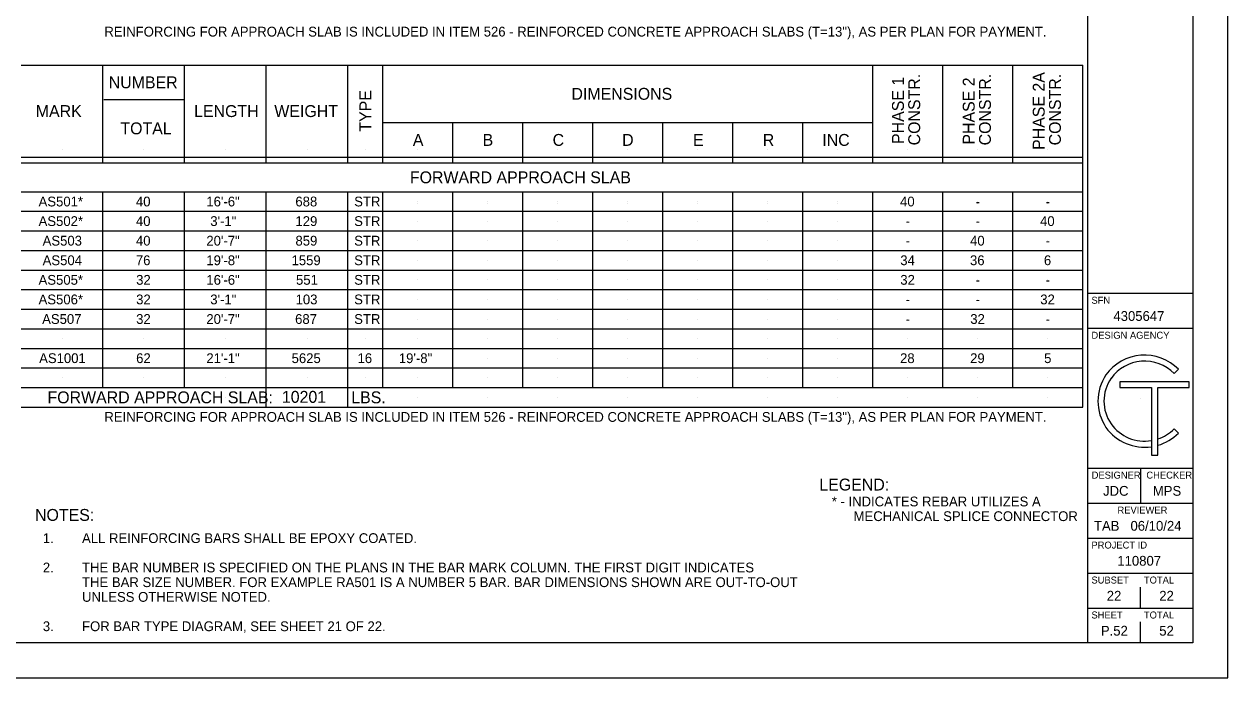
# Model space of a CAD drawing. Extents: x 0 to 34, y 0 to 22.
# Drawn here: x 16.8 to 34, y 0 to 9.35 of the extents above; entities that cross this region are included whole.
import ezdxf

# ---------------------------------------------------------------- set-up
doc = ezdxf.new("R2010")
doc.units = 0
for name, color, linetype in [('BR_P_Gen_Text', 7, 'Continuous'), ('SH_Border', 7, 'Continuous'), ('SH_Cut_Line', 7, 'Continuous'), ('SH_Data', 7, 'Continuous'), ('SH_Text', 7, 'Continuous')]:
    doc.layers.add(name, color=color, linetype=linetype)

msp = doc.modelspace()

# ---------------------------------------------------------------- linework, layer by layer
at = {"layer": 'BR_P_Gen_Text'}
for p, q in [((16.76, 8.763), (31.927, 8.764)), ((17.927, 7.363), (17.927, 8.763)), ((19.094, 7.363), (19.094, 8.763)), ((20.26, 7.364), (20.26, 8.763)), ((21.427, 7.364), (21.427, 8.763)), ((21.927, 7.364), (21.927, 8.763)), ((28.927, 7.363), (28.927, 8.764)), ((29.927, 7.363), (29.927, 8.764)), ((30.927, 7.363), (30.927, 8.764)), ((31.927, 3.872), (31.927, 8.764)), ((17.941, 8.269), (19.094, 8.269)), ((21.927, 7.94), (28.927, 7.94)), ((22.927, 7.363), (22.927, 7.94)), ((23.927, 7.363), (23.927, 7.94)), ((24.927, 7.363), (24.927, 7.94)), ((25.927, 7.363), (25.927, 7.94)), ((26.927, 7.363), (26.927, 7.94)), ((27.927, 7.363), (27.927, 7.94)), ((16.76, 7.446), (31.927, 7.446)), ((17.344, 7.561), (17.344, 7.561)), ((17.344, 7.561), (17.344, 7.561)), ((18.51, 7.561), (18.51, 7.561)), ((18.51, 7.561), (18.51, 7.561)), ((19.677, 7.561), (19.677, 7.561)), ((19.677, 7.561), (19.677, 7.561)), ((20.844, 7.561), (20.844, 7.561)), ((20.844, 7.561), (20.844, 7.561)), ((21.677, 7.561), (21.677, 7.561)), ((21.677, 7.561), (21.677, 7.561)), ((22.427, 7.561), (22.427, 7.561)), ((22.427, 7.561), (22.427, 7.561)), ((24.427, 7.561), (24.427, 7.561)), ((24.427, 7.561), (24.427, 7.561)), ((25.427, 7.561), (25.427, 7.561)), ((25.427, 7.561), (25.427, 7.561)), ((26.427, 7.561), (26.427, 7.561)), ((26.427, 7.561), (26.427, 7.561)), ((27.427, 7.561), (27.427, 7.561)), ((27.427, 7.561), (27.427, 7.561)), ((28.427, 7.561), (28.427, 7.561)), ((28.427, 7.561), (28.427, 7.561)), ((29.427, 7.561), (29.427, 7.561)), ((30.427, 7.561), (30.427, 7.561)), ((31.427, 7.561), (31.427, 7.561)), ((16.76, 7.363), (31.927, 7.363)), ((22.844, 7.158), (22.844, 7.158)), ((16.76, 6.952), (31.927, 6.952)), ((17.927, 4.152), (17.927, 6.952)), ((19.094, 4.152), (19.094, 6.952)), ((20.26, 3.872), (20.26, 6.952)), ((21.427, 3.872), (21.427, 6.952)), ((21.927, 4.152), (21.927, 6.952)), ((22.927, 4.152), (22.927, 6.952)), ((23.927, 4.152), (23.927, 6.952)), ((24.927, 4.152), (24.927, 6.952)), ((25.927, 4.152), (25.927, 6.952)), ((26.927, 4.152), (26.927, 6.952)), ((27.927, 4.152), (27.927, 6.952)), ((28.927, 4.152), (28.927, 6.952)), ((29.927, 4.152), (29.927, 6.952)), ((30.927, 4.152), (30.927, 6.952)), ((17.344, 6.812), (17.344, 6.812)), ((17.344, 6.778), (17.344, 6.778)), ((17.344, 6.778), (17.344, 6.778)), ((18.51, 6.812), (18.51, 6.812)), ((18.51, 6.778), (18.51, 6.778)), ((18.51, 6.778), (18.51, 6.778)), ((19.677, 6.812), (19.677, 6.812)), ((19.677, 6.778), (19.677, 6.778)), ((19.677, 6.778), (19.677, 6.778)), ((20.844, 6.812), (20.844, 6.812)), ((20.844, 6.778), (20.844, 6.778)), ((20.844, 6.778), (20.844, 6.778)), ((21.677, 6.812), (21.677, 6.812)), ((21.677, 6.778), (21.677, 6.778)), ((21.677, 6.778), (21.677, 6.778)), ((22.427, 6.812), (22.427, 6.812)), ((22.427, 6.778), (22.427, 6.778)), ((23.427, 6.812), (23.427, 6.812)), ((23.427, 6.778), (23.427, 6.778)), ((24.427, 6.812), (24.427, 6.812)), ((24.427, 6.778), (24.427, 6.778)), ((25.427, 6.812), (25.427, 6.812)), ((25.427, 6.778), (25.427, 6.778)), ((26.427, 6.812), (26.427, 6.812)), ((26.427, 6.778), (26.427, 6.778)), ((27.427, 6.812), (27.427, 6.812)), ((27.427, 6.778), (27.427, 6.778)), ((28.427, 6.812), (28.427, 6.812)), ((28.427, 6.778), (28.427, 6.778)), ((29.427, 6.812), (29.427, 6.812)), ((29.427, 6.778), (29.427, 6.778)), ((30.427, 6.812), (30.427, 6.812)), ((30.427, 6.778), (30.427, 6.778)), ((31.427, 6.812), (31.427, 6.812)), ((31.427, 6.778), (31.427, 6.778)), ((16.76, 6.672), (31.927, 6.672)), ((16.76, 6.392), (31.927, 6.392)), ((17.344, 6.532), (17.344, 6.532)), ((18.51, 6.532), (18.51, 6.532)), ((19.677, 6.532), (19.677, 6.532)), ((20.844, 6.532), (20.844, 6.532)), ((21.677, 6.532), (21.677, 6.532)), ((22.427, 6.532), (22.427, 6.532)), ((23.427, 6.532), (23.427, 6.532)), ((24.427, 6.532), (24.427, 6.532)), ((25.427, 6.532), (25.427, 6.532)), ((26.427, 6.532), (26.427, 6.532)), ((27.427, 6.532), (27.427, 6.532)), ((28.427, 6.532), (28.427, 6.532)), ((29.427, 6.532), (29.427, 6.532)), ((30.427, 6.532), (30.427, 6.532)), ((31.427, 6.532), (31.427, 6.532)), ((17.344, 6.252), (17.344, 6.252)), ((18.51, 6.252), (18.51, 6.252)), ((19.677, 6.252), (19.677, 6.252)), ((20.844, 6.252), (20.844, 6.252)), ((21.677, 6.252), (21.677, 6.252)), ((22.427, 6.252), (22.427, 6.252)), ((23.427, 6.252), (23.427, 6.252)), ((24.427, 6.252), (24.427, 6.252)), ((25.427, 6.252), (25.427, 6.252)), ((26.427, 6.252), (26.427, 6.252)), ((27.427, 6.252), (27.427, 6.252)), ((28.427, 6.252), (28.427, 6.252)), ((30.427, 6.252), (30.427, 6.252)), ((31.427, 6.252), (31.427, 6.252)), ((16.76, 6.112), (31.927, 6.112)), ((17.344, 5.972), (17.344, 5.972)), ((22.427, 5.972), (22.427, 5.972)), ((23.427, 5.972), (23.427, 5.972)), ((24.427, 5.972), (24.427, 5.972)), ((25.427, 5.972), (25.427, 5.972)), ((26.427, 5.972), (26.427, 5.972)), ((27.427, 5.972), (27.427, 5.972)), ((28.427, 5.972), (28.427, 5.972)), ((29.427, 5.972), (29.427, 5.972)), ((30.427, 5.972), (30.427, 5.972)), ((31.427, 5.972), (31.427, 5.972)), ((16.76, 5.832), (31.927, 5.832)), ((17.344, 5.692), (17.344, 5.692)), ((18.51, 5.692), (18.51, 5.692)), ((19.677, 5.692), (19.677, 5.692)), ((20.844, 5.692), (20.844, 5.692)), ((21.677, 5.692), (21.677, 5.692)), ((22.427, 5.692), (22.427, 5.692)), ((23.427, 5.692), (23.427, 5.692)), ((24.427, 5.692), (24.427, 5.692)), ((25.427, 5.692), (25.427, 5.692)), ((26.427, 5.692), (26.427, 5.692)), ((27.427, 5.692), (27.427, 5.692)), ((28.427, 5.692), (28.427, 5.692)), ((29.427, 5.692), (29.427, 5.692)), ((30.427, 5.692), (30.427, 5.692)), ((31.427, 5.692), (31.427, 5.692)), ((16.76, 5.552), (31.927, 5.552)), ((17.344, 5.412), (17.344, 5.412)), ((18.51, 5.412), (18.51, 5.412)), ((19.677, 5.412), (19.677, 5.412)), ((20.844, 5.412), (20.844, 5.412)), ((21.677, 5.412), (21.677, 5.412)), ((22.427, 5.412), (22.427, 5.412)), ((23.427, 5.412), (23.427, 5.412)), ((24.427, 5.412), (24.427, 5.412)), ((25.427, 5.412), (25.427, 5.412)), ((26.427, 5.412), (26.427, 5.412)), ((27.427, 5.412), (27.427, 5.412)), ((28.427, 5.412), (28.427, 5.412)), ((29.427, 5.412), (29.427, 5.412)), ((30.427, 5.412), (30.427, 5.412)), ((31.427, 5.412), (31.427, 5.412)), ((16.76, 5.272), (31.927, 5.272)), ((16.76, 4.992), (31.927, 4.992)), ((17.344, 5.132), (17.344, 5.132)), ((18.51, 5.132), (18.51, 5.132)), ((19.677, 5.132), (19.677, 5.132)), ((20.844, 5.132), (20.844, 5.132)), ((21.677, 5.132), (21.677, 5.132)), ((22.427, 5.132), (22.427, 5.132)), ((23.427, 5.132), (23.427, 5.132)), ((24.427, 5.132), (24.427, 5.132)), ((25.427, 5.132), (25.427, 5.132)), ((26.427, 5.132), (26.427, 5.132)), ((27.427, 5.132), (27.427, 5.132)), ((28.427, 5.132), (28.427, 5.132)), ((29.427, 5.132), (29.427, 5.132)), ((30.427, 5.132), (30.427, 5.132)), ((31.427, 5.132), (31.427, 5.132)), ((17.344, 4.852), (17.344, 4.852)), ((17.344, 4.852), (17.344, 4.852)), ((18.51, 4.852), (18.51, 4.852)), ((18.51, 4.852), (18.51, 4.852)), ((19.677, 4.852), (19.677, 4.852)), ((19.677, 4.852), (19.677, 4.852)), ((20.844, 4.852), (20.844, 4.852)), ((20.844, 4.852), (20.844, 4.852)), ((21.677, 4.852), (21.677, 4.852)), ((21.677, 4.852), (21.677, 4.852)), ((22.427, 4.852), (22.427, 4.852)), ((22.427, 4.852), (22.427, 4.852)), ((23.427, 4.852), (23.427, 4.852)), ((23.427, 4.852), (23.427, 4.852)), ((24.427, 4.852), (24.427, 4.852)), ((24.427, 4.852), (24.427, 4.852)), ((25.427, 4.852), (25.427, 4.852)), ((25.427, 4.852), (25.427, 4.852)), ((26.427, 4.852), (26.427, 4.852)), ((26.427, 4.852), (26.427, 4.852)), ((27.427, 4.852), (27.427, 4.852)), ((27.427, 4.852), (27.427, 4.852)), ((28.427, 4.852), (28.427, 4.852)), ((28.427, 4.852), (28.427, 4.852)), ((29.427, 4.852), (29.427, 4.852)), ((30.427, 4.852), (30.427, 4.852)), ((31.427, 4.852), (31.427, 4.852)), ((16.76, 4.712), (31.927, 4.712)), ((17.344, 4.572), (17.344, 4.572)), ((17.344, 4.572), (17.344, 4.572)), ((18.51, 4.572), (18.51, 4.572)), ((18.51, 4.572), (18.51, 4.572)), ((19.677, 4.572), (19.677, 4.572)), ((19.677, 4.572), (19.677, 4.572)), ((20.844, 4.572), (20.844, 4.572)), ((20.844, 4.572), (20.844, 4.572)), ((21.677, 4.572), (21.677, 4.572)), ((21.677, 4.572), (21.677, 4.572)), ((22.427, 4.572), (22.427, 4.572)), ((22.427, 4.572), (22.427, 4.572)), ((23.427, 4.572), (23.427, 4.572)), ((23.427, 4.572), (23.427, 4.572)), ((24.427, 4.572), (24.427, 4.572)), ((24.427, 4.572), (24.427, 4.572)), ((25.427, 4.572), (25.427, 4.572)), ((25.427, 4.572), (25.427, 4.572)), ((26.427, 4.572), (26.427, 4.572)), ((26.427, 4.572), (26.427, 4.572)), ((27.427, 4.572), (27.427, 4.572)), ((27.427, 4.572), (27.427, 4.572)), ((28.427, 4.572), (28.427, 4.572)), ((28.427, 4.572), (28.427, 4.572)), ((29.427, 4.572), (29.427, 4.572)), ((29.427, 4.572), (29.427, 4.572)), ((30.427, 4.572), (30.427, 4.572)), ((30.427, 4.572), (30.427, 4.572)), ((31.427, 4.572), (31.427, 4.572)), ((31.427, 4.572), (31.427, 4.572)), ((16.76, 4.432), (31.927, 4.432)), ((16.76, 4.152), (31.927, 4.152)), ((17.344, 4.292), (17.344, 4.292)), ((18.51, 4.292), (18.51, 4.292)), ((19.677, 4.292), (19.677, 4.292)), ((20.844, 4.292), (20.844, 4.292)), ((21.677, 4.292), (21.677, 4.292)), ((22.427, 4.292), (22.427, 4.292)), ((23.427, 4.292), (23.427, 4.292)), ((24.427, 4.292), (24.427, 4.292)), ((25.427, 4.292), (25.427, 4.292)), ((26.427, 4.292), (26.427, 4.292)), ((27.427, 4.292), (27.427, 4.292)), ((28.427, 4.292), (28.427, 4.292)), ((29.427, 4.292), (29.427, 4.292)), ((30.427, 4.292), (30.427, 4.292)), ((31.427, 4.292), (31.427, 4.292)), ((17.344, 4.012), (17.344, 4.012)), ((18.51, 4.012), (18.51, 4.012)), ((19.677, 4.012), (19.677, 4.012)), ((20.844, 4.012), (20.844, 4.012)), ((21.677, 4.012), (21.677, 4.012)), ((22.427, 4.012), (22.427, 4.012)), ((23.427, 4.012), (23.427, 4.012)), ((24.427, 4.012), (24.427, 4.012)), ((25.427, 4.012), (25.427, 4.012)), ((26.427, 4.012), (26.427, 4.012)), ((27.427, 4.012), (27.427, 4.012)), ((28.427, 4.012), (28.427, 4.012)), ((29.427, 4.012), (29.427, 4.012)), ((30.427, 4.012), (30.427, 4.012)), ((31.427, 4.012), (31.427, 4.012)), ((16.76, 3.872), (31.927, 3.872))]:
    msp.add_line(p, q, dxfattribs=at)
at = {"layer": 'SH_Border'}
for p, q in [((32, 0.5), (32, 21.5)), ((32, 5.5), (33.5, 5.5)), ((32, 5), (33.5, 5)), ((32, 3), (33.5, 3)), ((32.75, 3), (32.75, 2.5)), ((32, 2.5), (33.5, 2.5)), ((32, 2), (33.5, 2)), ((32, 1.5), (33.5, 1.5)), ((32, 1), (33.5, 1))]:
    msp.add_line(p, q, dxfattribs=at)
msp.add_lwpolyline([(1.5, 21.5), (33.5, 21.5), (33.5, 0.5), (1.5, 0.5)], close=True, dxfattribs=at)
at = {"layer": 'SH_Cut_Line'}
msp.add_lwpolyline([(0, 0), (34, 0), (34, 22), (0, 22)], close=True, dxfattribs=at)
at = {"layer": 'SH_Data'}
for p, q in [((32.75, 4), (32.75, 4)), ((32.75, 1), (32.75, 1.3)), ((32.75, 0.5), (32.75, 0.8)), ((32.375, 0.675), (32.375, 0.675))]:
    msp.add_line(p, q, dxfattribs=at)
at = {"layer": 'SH_Text'}
for p, q in [((33.293, 4.415), (33.231, 4.354)), ((33.293, 4.415), (33.231, 4.354)), ((33.446, 4.234), (32.458, 4.234)), ((32.458, 4.234), (32.458, 4.152)), ((32.458, 4.152), (32.907, 4.152)), ((32.907, 4.152), (32.907, 3.186)), ((33, 3.186), (33, 4.152)), ((33, 4.152), (33.446, 4.152)), ((33.446, 4.152), (33.446, 4.234)), ((33.231, 3.562), (33.293, 3.5)), ((33.231, 3.562), (33.293, 3.5)), ((32.907, 3.394), (32.907, 3.306)), ((32.907, 3.394), (32.907, 3.306)), ((33, 3.326), (33, 3.417)), ((33, 3.326), (33, 3.417)), ((32.907, 3.186), (33, 3.186))]:
    msp.add_line(p, q, dxfattribs=at)
msp.add_lwpolyline([(32.907, 4.152), (32.907, 3.186), (33, 3.186), (33, 4.152), (33.446, 4.152), (33.446, 4.234), (32.458, 4.234), (32.458, 4.152)], close=True, dxfattribs=at)
for centre, radius, start, end in [((32.81, 3.936), 0.68, 44.7027, 144.3276), ((32.81, 3.936), 0.68, 44.7027, 144.3276), ((32.81, 3.936), 0.593, 44.7362, 144.1102), ((32.81, 3.936), 0.593, 44.7362, 144.1102), ((32.808, 3.958), 0.666, 145.7329, 214.2671), ((32.808, 3.958), 0.666, 145.7329, 214.2671), ((32.808, 3.958), 0.579, 145.7266, 214.2734), ((32.808, 3.958), 0.579, 145.7266, 214.2734), ((32.81, 3.979), 0.593, 215.8898, 279.4882), ((32.81, 3.979), 0.593, 215.8898, 279.4882), ((32.81, 3.979), 0.68, 215.6724, 278.2613), ((32.81, 3.979), 0.68, 215.6724, 278.2613), ((32.81, 3.979), 0.593, 288.6992, 315.2638), ((32.81, 3.979), 0.593, 288.6992, 315.2638), ((32.81, 3.979), 0.68, 286.2291, 315.2973), ((32.81, 3.979), 0.68, 286.2291, 315.2973)]:
    msp.add_arc(centre, radius, start, end, dxfattribs=at)

# ---------------------------------------------------------------- texts
at = {"layer": 'BR_P_Gen_Text'}
for s, height, p in [('REINFORCING FOR APPROACH SLAB IS INCLUDED IN ITEM 526 - REINFORCED CONCRETE APPROACH SLABS (T=13"), AS PER PLAN FOR PAYMENT.', 0.14, (17.948, 9.171)), ('NUMBER', 0.17, (18.01, 8.431)), ('DIMENSIONS', 0.17, (24.621, 8.267)), ('MARK', 0.17, (16.968, 8.02)), ('LENGTH', 0.17, (19.23, 8.02)), ('WEIGHT', 0.17, (20.376, 8.02)), ('TOTAL', 0.17, (18.177, 7.773)), ('A', 0.17, (22.355, 7.608)), ('B', 0.17, (23.352, 7.608)), ('C', 0.17, (24.352, 7.608)), ('D', 0.17, (25.345, 7.608)), ('E', 0.17, (26.358, 7.608)), ('R', 0.17, (27.354, 7.608)), ('INC', 0.17, (28.204, 7.608)), ('FORWARD APPROACH SLAB', 0.17, (22.313, 7.073)), ('AS501*', 0.14, (17.008, 6.742)), ('40', 0.14, (18.399, 6.742)), ('16\'-6"', 0.14, (19.405, 6.742)), ('688', 0.14, (20.677, 6.742)), ('STR', 0.14, (21.517, 6.742)), ('40', 0.14, (29.316, 6.742)), ('-', 0.14, (30.396, 6.742)), ('-', 0.14, (31.396, 6.742)), ('AS502*', 0.14, (17.008, 6.462)), ('40', 0.14, (18.399, 6.462)), ('3\'-1"', 0.14, (19.461, 6.462)), ('129', 0.14, (20.678, 6.462)), ('STR', 0.14, (21.517, 6.462)), ('40', 0.14, (31.316, 6.462)), ('-', 0.14, (29.396, 6.462)), ('-', 0.14, (30.396, 6.462)), ('AS503', 0.14, (17.066, 6.182)), ('40', 0.14, (18.399, 6.182)), ('20\'-7"', 0.14, (19.405, 6.182)), ('859', 0.14, (20.678, 6.182)), ('STR', 0.14, (21.517, 6.182)), ('-', 0.14, (29.396, 6.182)), ('40', 0.14, (30.316, 6.182)), ('-', 0.14, (31.396, 6.182)), ('AS504', 0.14, (17.066, 5.902)), ('76', 0.14, (18.398, 5.902)), ('19\'-8"', 0.14, (19.405, 5.902)), ('1559', 0.14, (20.622, 5.902)), ('STR', 0.14, (21.517, 5.902)), ('34', 0.14, (29.319, 5.902)), ('36', 0.14, (30.315, 5.902)), ('6', 0.14, (31.371, 5.902)), ('AS505*', 0.14, (17.008, 5.622)), ('32', 0.14, (18.402, 5.622)), ('16\'-6"', 0.14, (19.405, 5.622)), ('551', 0.14, (20.686, 5.622)), ('STR', 0.14, (21.517, 5.622)), ('32', 0.14, (29.319, 5.622)), ('-', 0.14, (30.396, 5.622)), ('-', 0.14, (31.396, 5.622)), ('AS506*', 0.14, (17.008, 5.342)), ('32', 0.14, (18.402, 5.342)), ('3\'-1"', 0.14, (19.461, 5.342)), ('103', 0.14, (20.68, 5.342)), ('STR', 0.14, (21.517, 5.342)), ('-', 0.14, (29.396, 5.342)), ('-', 0.14, (30.396, 5.342)), ('32', 0.14, (31.319, 5.342)), ('AS507', 0.14, (17.059, 5.062)), ('32', 0.14, (18.402, 5.062)), ('20\'-7"', 0.14, (19.405, 5.062)), ('687', 0.14, (20.673, 5.062)), ('STR', 0.14, (21.517, 5.062)), ('32', 0.14, (30.319, 5.062)), ('-', 0.14, (29.396, 5.062)), ('-', 0.14, (31.396, 5.062)), ('AS1001', 0.14, (17.016, 4.502)), ('62', 0.14, (18.402, 4.502)), ('21\'-1"', 0.14, (19.405, 4.502)), ('5625', 0.14, (20.623, 4.502)), ('16', 0.14, (21.565, 4.502)), ('19\'-8"', 0.14, (22.155, 4.502)), ('28', 0.14, (29.316, 4.502)), ('29', 0.14, (30.317, 4.502)), ('5', 0.14, (31.374, 4.502)), ('FORWARD APPROACH SLAB:', 0.17, (17.135, 3.927)), ('10201', 0.17, (20.484, 3.934)), ('LBS.', 0.17, (21.475, 3.927)), ('REINFORCING FOR APPROACH SLAB IS INCLUDED IN ITEM 526 - REINFORCED CONCRETE APPROACH SLABS (T=13"), AS PER PLAN FOR PAYMENT.', 0.14, (17.948, 3.662)), ('LEGEND:', 0.17, (28.163, 2.68)), ('* - INDICATES REBAR UTILIZES A', 0.14, (28.34, 2.453)), ('NOTES:', 0.17, (16.957, 2.246)), ('      MECHANICAL SPLICE CONNECTOR', 0.14, (28.34, 2.243)), ('1.', 0.14, (17.069, 1.929)), ('ALL REINFORCING BARS SHALL BE EPOXY COATED.', 0.14, (17.629, 1.929)), ('2.', 0.14, (17.069, 1.509)), ('THE BAR NUMBER IS SPECIFIED ON THE PLANS IN THE BAR MARK COLUMN. THE FIRST DIGIT INDICATES', 0.14, (17.629, 1.509)), ('THE BAR SIZE NUMBER. FOR EXAMPLE RA501 IS A NUMBER 5 BAR. BAR DIMENSIONS SHOWN ARE OUT-TO-OUT', 0.14, (17.629, 1.299)), ('UNLESS OTHERWISE NOTED.', 0.14, (17.629, 1.089)), ('3.', 0.14, (17.069, 0.669)), ('FOR BAR TYPE DIAGRAM, SEE SHEET 21 OF 22.', 0.14, (17.629, 0.669))]:
    msp.add_text(s, height=height, dxfattribs=at).set_placement(p)
for s, p in [('CONSTR.', (29.603, 7.615)), ('CONSTR.', (30.614, 7.615)), ('PHASE 2A', (31.382, 7.55)), ('CONSTR.', (31.614, 7.615)), ('PHASE 1', (29.371, 7.635)), ('PHASE 2', (30.382, 7.626)), ('TYPE', (21.762, 7.811))]:
    msp.add_text(s, height=0.17, rotation=90, dxfattribs=at).set_placement(p)
at = {"layer": 'SH_Data'}
for s, height, p in [('SFN', 0.1, (32.05, 5.35)), ('4305647', 0.14, (32.364, 5.105)), ('DESIGN AGENCY', 0.1, (32.05, 4.85)), ('DESIGNER', 0.1, (32.054, 2.85)), ('CHECKER', 0.1, (32.835, 2.85)), ('JDC', 0.14, (32.216, 2.605)), ('MPS', 0.14, (32.927, 2.605)), ('REVIEWER', 0.1, (32.422, 2.35)), ('TAB', 0.14, (32.086, 2.105)), ('06/10/24', 0.14, (32.608, 2.105)), ('PROJECT ID', 0.1, (32.05, 1.85)), ('110807', 0.14, (32.42, 1.605)), ('SUBSET', 0.1, (32.05, 1.35)), ('TOTAL', 0.1, (32.8, 1.35)), ('22', 0.14, (32.269, 1.105)), ('22', 0.14, (33.019, 1.105)), ('SHEET', 0.1, (32.05, 0.85)), ('TOTAL', 0.1, (32.8, 0.85)), ('P.52', 0.14, (32.185, 0.605)), ('52', 0.14, (33.019, 0.605))]:
    msp.add_text(s, height=height, dxfattribs=at).set_placement(p)

doc.saveas('drawing.dxf')
